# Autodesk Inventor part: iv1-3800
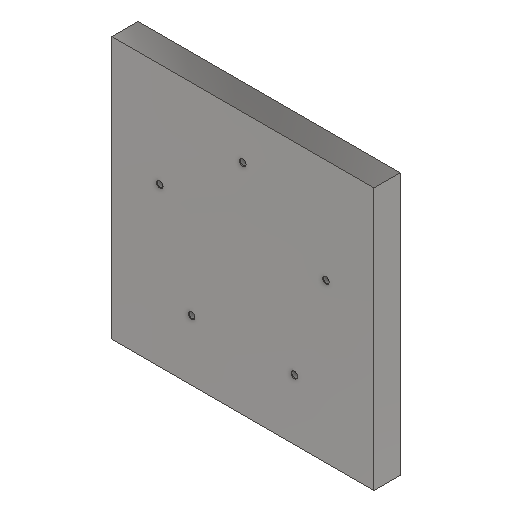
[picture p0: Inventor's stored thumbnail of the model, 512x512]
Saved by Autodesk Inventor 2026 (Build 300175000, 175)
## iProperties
Created: 2022-01
Part Number: iv1-3800
Material: Steel, Mild
Document SubType Name: Modeling
Designer: Lars Bertram Pedersen
Density: 7.85 g/cm^3
Appearance: Semi-Polished
Mass: 21169.5 g
Surface Area: 2178.79 cm^2
Volume: 2696.75 cm^3
Author: Lars Bertram Pedersen
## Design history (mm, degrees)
sketch "Sketch1" dims "d1" = 200
  geometry: L1 (-150, -150)-(150, -150); L2 (150, -150)-(150, 150); L3 (150, 150)-(-150, 150); L4 (-150, 150)-(-150, -150); L5 (-150, -150)-(150, 150); L6 (150, -150)-(-150, 150); 8 further points
  constraints: 12 end point, 3 midpoint, 2 parallel, 2 perpendicular, 2 vertical alignment, 1 coincident, 1 horizontal, 8 other
  dimensions: "d0" = 300 distance of L2.end L3.end; "d4" = 360 deg dimension on point (0, 0) point (0, 100) (derived)
extrude "Extrusion1" new body sketch "Sketch1" distance "d6" = 30; taper "d7" = 0 deg
hole "Hole1" sketch "Sketch1" diameter "d8" = 6.647; stored, may be unused: countersink angle "d12" = 90 deg, drill point angle "d14" = 118 deg; dims "d9" = 14, "d10" = 17.3, "d11" = 4.775, "d13" = 18
chamfer "Chamfer1" distance "d15" = 0.5; stored, may be unused: second distance "d16" = 2, angle "d17" = 45 deg
body "Solid1"
node "Sketch Circular Pattern1" dims "d4" = 360 deg (derived)
